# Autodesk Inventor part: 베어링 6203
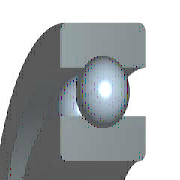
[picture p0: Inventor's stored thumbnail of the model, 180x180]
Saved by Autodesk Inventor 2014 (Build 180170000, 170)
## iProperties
IsCustomPart: 0
Company: 한국ATC센터
Created: 2015-11
Part Number: 베어링 6203
Material: 강철, 연강
Description: 깊은 그루브 볼 베어링
Document SubType Name: Modeling
Standard: KS B 2023
Designer: mdu
Standards Organization: KS
Language: ko-KR
Size Designation: 6203 - 17 x 40 x 12
Categories: <MemberInstance><Categories><Category DisplayName="샤프트 부품" InternalName="7f7aeb1f-a693-4053-b835-cee3144e0d98" Mnemonic="SHFT"><Category DisplayName="베어링" Inter
Density: 7.86 g/cm^3
Mass: 58.8203 g
Surface Area: 64.3582 cm^2
Volume: 7.4835 cm^3
Appearance: 노란색
Author: mdu
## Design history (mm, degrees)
sketch "스케치" dims "d0" = 5.98 (= -0.26 x WD + 0.26 x BD)
  geometry: L1 (3.01, 14.25)-(8.99, 14.25); L2 (6, 14.25)-(6, 11.26); L3 (6, 14.25)-(6, 17.24); L4 (3.778, 12.249)-(0, 12.249); L5 (0, 8.5)-(12, 8.5); L6 (3.778, 16.251)-(0, 16.251); L7 (0, 20)-(12, 20); L8 (12, 8.5)-(12, 12.249); L9 (8.222, 12.249)-(12, 12.249); L10 (8.222, 16.251)-(12, 16.251); L11 (12, 20)-(12, 16.251); L12 (-1.4, 0)-(8.4, 0) reference; L13 (0, -0.3)-(0, 5.3) reference
  constraints: 22 end point, 4 point on line, 2 collinear, 2 perpendicular, 2 symmetric about line, 1 midpoint, 1 parallel, 14 other
  dimensions: "d9" = 17 diameter of L5 L12 (= WD); "d11" = 40 diameter of L7 L12 (= BD); "d12" = 12 distance between parallel lines of L8 L13 (= KB); "d13" = 24.498 diameter of L9 L12 (= 0.326 x BD + 0.674 x WD)
revolve "본체" stored, may be unused: angle "d6" = 90 deg
revolve "볼" stored, may be unused: angle "d7" = 90 deg
pattern_circular "IDS_ARRAYBALL[SIMPL:T]" dims angle "d3" = 360 deg
body "Solid1"
fillet "모깎기1" dims "d1" = 0.6 (= KRS)
other parameters: "WD" = 17 [user parameter; used in 5 equation terms], "BD" = 40 [user parameter; used in 5 equation terms], "KB" = 12 [user parameter; used in 1 equation term], "KRS" = 0.6 [user parameter; used in 1 equation term], "d4" = 0, "d5" = 0, "d8" = 0, "d14" = 0, "d15" = 0, "BBA" = 0 [user parameter], "BC0" = 4750000 [user parameter], "BC" = 9560000 [user parameter], "WR" = 8.5 (= 0.5 x WD) [user parameter]
